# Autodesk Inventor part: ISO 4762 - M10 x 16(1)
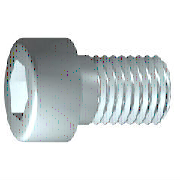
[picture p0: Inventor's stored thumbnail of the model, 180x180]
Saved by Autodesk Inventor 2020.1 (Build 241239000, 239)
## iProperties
Created: 2019-01
Part Number: ISO 4762 - M10 x 16(1)
Material: Edelstahl, 440C
Description: Innensechskantschraube
Document SubType Name: Modeling
Standard: ISO 4762
Designer: lutzd
Standard Revision: Fourth edition 2004-03-01
Standards Organization: ISO
Language: de-DE
Size Designation: M10 x 16
Categories: <MemberInstance><Categories><Category DisplayName="Verbindungselemente" InternalName="e4da775c-781d-43d5-af7c-5136215cf5a6" Mnemonic="FSTN"><Category DisplayNam
Mass: 22.547 g
Surface Area: 15.1968 cm^2
Volume: 2.90929 cm^3
Density: 7.75 g/cm^3
Appearance: Halbpoliert
IsCustomPart: 0
Author: lutzd
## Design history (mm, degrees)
body "Solid1"
sketch "Skizze1"
  geometry: L1 (-2.333, 0)-(16, 0); L2 (16, 0)-(16, 5); L3 (16, 5)-(3.75, 5); L4 (3.75, 5)-(2.83, 5); L5 (2.83, 5)-(0, 5); L6 (0, 5)-(0, 8); L7 (0, 8)-(-10, 8); L8 (-10, 8)-(-10, 4.619); L9 (-10, 4.619)-(-5, 4.619); L10 (-5, 4.619)-(-2.333, 0); L11 (-15.2, 0)-(21.2, 0) reference; L12 (0, -1.6)-(0, 9.6) reference; L13 (3.75, 5)-(0, 5)
  constraints: 22 end point, 6 parallel, 2 collinear, 2 perpendicular, 1 horizontal, 1 point on line
  dimensions: "d1" = 12.25 distance from line of L3.end L2 (= GEL); "d2" = 0.92028 distance of L4.end L3.end (computed from GAL); "d3" = 10 distance between parallel lines of L8 L6 (= KOH); "d4" = 5 distance of L8.end L9.end (= INTI); "d5" = 60 deg angle of L10 L1; "d6" = 10 diameter of L3 L1 (= GD); "d7" = 10 diameter of L5 L1 (= BDM); "d8" = 9.2376 diameter of L9 L1 (= 1.1547 x SW); "d9" = 16 diameter of L7 L1 (= KOD); "d26" = 16 distance between parallel lines of L12 L2 (= NLG)
workplane "Work Plane1"
fillet "Fillet2" dims "d30" = 0.1 (= R)
revolve "Körper" stored, may be unused: angle "d10" = 90 deg
sketch "Skizze2"
  geometry: L1 (0, -11.2)-(0, 11.2) reference; L2 (-11.2, 0)-(11.2, 0) reference; L3 (4.619, 0)-(2.309, -4); L4 (2.309, -4)-(-2.309, -4); L5 (-2.309, -4)-(-4.619, 0); L6 (-4.619, 0)-(-2.309, 4); L7 (-2.309, 4)-(2.309, 4); L8 (2.309, 4)-(4.619, 0); 2 further points
  constraints: 12 end point, 1 coincident, 1 horizontal alignment, 1 point on line, 12 other
extrude "Loch" join sketch "Skizze2" stored distance "d11" = 10; taper "d12" = 0 deg
fillet "Rundung1" dims "d17" = 1 (= RR)
feature "Gewinde" dims "d13" = 12.25 (= GEL), "d14" = 0
chamfer "Fase1" distance "d15" = 0.92018 (= -0.5 x SPD + 0.5 x GD); stored, may be unused: second distance "d16" = 0.92018 (= GUL), angle "d27" = 45 deg
other parameters: "GD" = 10 [user parameter; used in 2 equation terms], "NLG" = 16 [user parameter; used in 1 equation term], "GEL" = 12.25 [user parameter; used in 2 equation terms], "KOD" = 16 [user parameter; used in 1 equation term], "KOH" = 10 [user parameter; used in 1 equation term], "INTI" = 5 [user parameter; used in 1 equation term], "GAL" = 0.92018 (= 0.61345 x PTC) [user parameter; used in 1 equation term], "GUL" = 0.92018 (= 0.61345 x PTC) [user parameter; used in 1 equation term], "BDM" = 10 (= NND) [user parameter; used in 1 equation term], "SW" = 8 [user parameter; used in 2 equation terms], "RR" = 1 [user parameter; used in 1 equation term], "SPD" = 8.15965 (= NND - 1.2269 x PTC) [user parameter; used in 1 equation term], "d19" = 0, "d28" = 0, "d29" = 0, "R" = 0.1 [user parameter; used in 1 equation term], "TOA" = 30 deg [user parameter], "GD1" = 8.15965 (= THREADDIA - 1.2269 x PTC) [user parameter], "FAWI" = 45 deg [user parameter], "TPU" = 6.66667 (computed from PTC) [user parameter], "PTC" = 1.5 [user parameter; used in 5 equation terms], "E0" = 9.24 (= 1.155 x SW) [user parameter]
